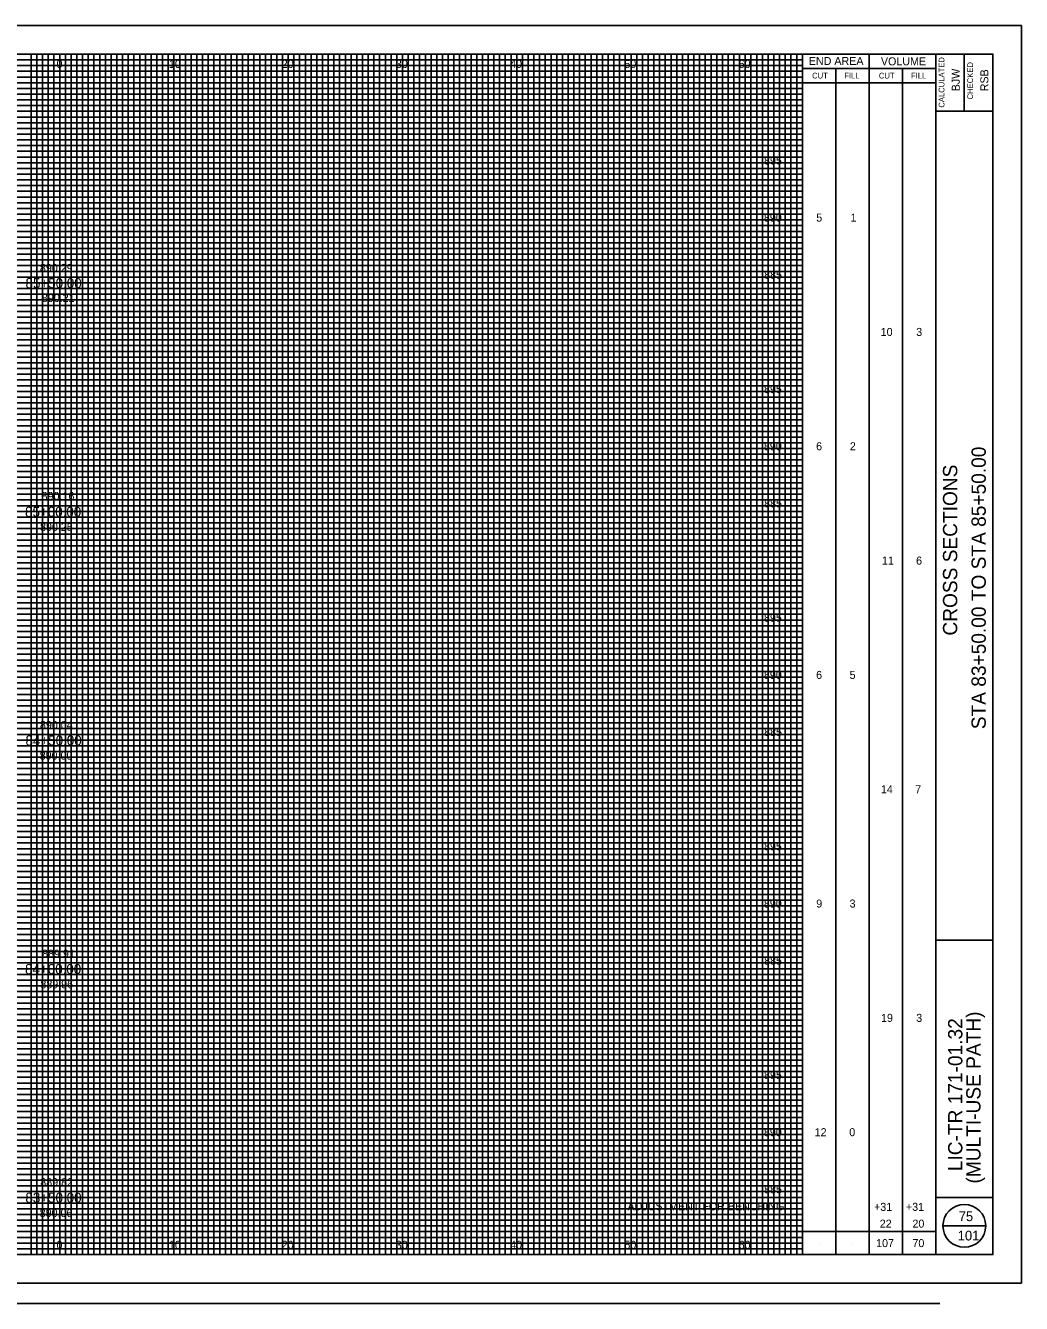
# Model space of a CAD drawing. Extents: x -10 to 160, y -2 to 3672.
# Drawn here: x 72.8 to 160, y 685.7 to 797.5 of the extents above; entities that cross this region are included whole.
import ezdxf

# ---------------------------------------------------------------- set-up
doc = ezdxf.new("R2010")
doc.units = 0
for name, color, linetype in [('SH_Border', 7, 'Continuous'), ('SH_Cut_Line', 7, 'Continuous'), ('SH_Data', 7, 'Continuous'), ('SH_Major_Grid_Line', 7, 'Continuous'), ('SH_Minor_Grid_Line', 7, 'Continuous'), ('SH_Text', 7, 'Continuous'), ('TX_P_10', 7, 'Continuous'), ('TX_X_10', 7, 'Continuous')]:
    doc.layers.add(name, color=color, linetype=linetype)

msp = doc.modelspace()

# ---------------------------------------------------------------- linework, layer by layer
at = {"layer": 'SH_Border'}
for p, q in [((152.5, 690), (152.5, 795)), ((155, 795), (155, 790)), ((152.5, 790), (157.5, 790)), ((152.5, 717.5), (157.5, 717.5)), ((152.5, 695), (157.5, 695))]:
    msp.add_line(p, q, dxfattribs=at)
msp.add_lwpolyline([(0, 795), (157.5, 795), (157.5, 690), (0, 690)], close=True, dxfattribs=at)
at = {"layer": 'SH_Cut_Line'}
msp.add_lwpolyline([(-10, 687.5), (160, 687.5), (160, 797.5), (-10, 797.5)], close=True, dxfattribs=at)
at = {"layer": 'SH_Data'}
for p, q in [((140.83, 690), (140.83, 795)), ((146.67, 690), (146.67, 795)), ((140.83, 793.75), (152.5, 793.75)), ((143.75, 690), (143.75, 793.75)), ((149.58, 690), (149.58, 793.75)), ((140.83, 792.5), (152.5, 792.5)), ((140.83, 692), (152.5, 692)), ((153.12, 692.5), (156.88, 692.5)), ((142.29, 691), (142.29, 691)), ((145.21, 691), (145.21, 691)), ((148.12, 691), (148.12, 691)), ((151.04, 691), (151.04, 691))]:
    msp.add_line(p, q, dxfattribs=at)
msp.add_circle((155, 692.5), 1.87, dxfattribs=at)
at = {"layer": 'SH_Major_Grid_Line'}
for p, q in [((75.83, 690), (75.83, 795)), ((80.83, 690), (80.83, 795)), ((85.83, 690), (85.83, 795)), ((90.83, 690), (90.83, 795)), ((95.83, 690), (95.83, 795)), ((100.83, 690), (100.83, 795)), ((105.83, 690), (105.83, 795)), ((110.83, 690), (110.83, 795)), ((115.83, 690), (115.83, 795)), ((120.83, 690), (120.83, 795)), ((125.83, 690), (125.83, 795)), ((130.83, 690), (130.83, 795)), ((135.83, 690), (135.83, 795)), ((5.83, 790), (140.83, 790)), ((5.83, 785), (140.83, 785)), ((5.83, 780), (140.83, 780)), ((5.83, 775), (140.83, 775)), ((5.83, 770), (140.83, 770)), ((5.83, 765), (140.83, 765)), ((5.83, 760), (140.83, 760)), ((5.83, 755), (140.83, 755)), ((5.83, 750), (140.83, 750)), ((5.83, 745), (140.83, 745)), ((5.83, 740), (140.83, 740)), ((5.83, 735), (140.83, 735)), ((5.83, 730), (140.83, 730)), ((5.83, 725), (140.83, 725)), ((5.83, 720), (140.83, 720)), ((5.83, 715), (140.83, 715)), ((5.83, 710), (140.83, 710)), ((5.83, 705), (140.83, 705)), ((5.83, 700), (140.83, 700)), ((5.83, 695), (140.83, 695)), ((17.85, 685.72), (152.85, 685.72))]:
    msp.add_line(p, q, dxfattribs=at)
at = {"layer": 'SH_Minor_Grid_Line'}
for p, q in [((73.33, 690), (73.33, 795)), ((73.83, 690), (73.83, 795)), ((74.33, 690), (74.33, 795)), ((74.83, 690), (74.83, 795)), ((75.33, 690), (75.33, 795)), ((76.33, 690), (76.33, 795)), ((76.83, 690), (76.83, 795)), ((77.33, 690), (77.33, 795)), ((77.83, 690), (77.83, 795)), ((78.33, 690), (78.33, 795)), ((78.83, 690), (78.83, 795)), ((79.33, 690), (79.33, 795)), ((79.83, 690), (79.83, 795)), ((80.33, 690), (80.33, 795)), ((81.33, 690), (81.33, 795)), ((81.83, 690), (81.83, 795)), ((82.33, 690), (82.33, 795)), ((82.83, 690), (82.83, 795)), ((83.33, 690), (83.33, 795)), ((83.83, 690), (83.83, 795)), ((84.33, 690), (84.33, 795)), ((84.83, 690), (84.83, 795)), ((85.33, 690), (85.33, 795)), ((86.33, 690), (86.33, 795)), ((86.83, 690), (86.83, 795)), ((87.33, 690), (87.33, 795)), ((87.83, 690), (87.83, 795)), ((88.33, 690), (88.33, 795)), ((88.83, 690), (88.83, 795)), ((89.33, 690), (89.33, 795)), ((89.83, 690), (89.83, 795)), ((90.33, 690), (90.33, 795)), ((91.33, 690), (91.33, 795)), ((91.83, 690), (91.83, 795)), ((92.33, 690), (92.33, 795)), ((92.83, 690), (92.83, 795)), ((93.33, 690), (93.33, 795)), ((93.83, 690), (93.83, 795)), ((94.33, 690), (94.33, 795)), ((94.83, 690), (94.83, 795)), ((95.33, 690), (95.33, 795)), ((96.33, 690), (96.33, 795)), ((96.83, 690), (96.83, 795)), ((97.33, 690), (97.33, 795)), ((97.83, 690), (97.83, 795)), ((98.33, 690), (98.33, 795)), ((98.83, 690), (98.83, 795)), ((99.33, 690), (99.33, 795)), ((99.83, 690), (99.83, 795)), ((100.33, 690), (100.33, 795)), ((101.33, 690), (101.33, 795)), ((101.83, 690), (101.83, 795)), ((102.33, 690), (102.33, 795)), ((102.83, 690), (102.83, 795)), ((103.33, 690), (103.33, 795)), ((103.83, 690), (103.83, 795)), ((104.33, 690), (104.33, 795)), ((104.83, 690), (104.83, 795)), ((105.33, 690), (105.33, 795)), ((106.33, 690), (106.33, 795)), ((106.83, 690), (106.83, 795)), ((107.33, 690), (107.33, 795)), ((107.83, 690), (107.83, 795)), ((108.33, 690), (108.33, 795)), ((108.83, 690), (108.83, 795)), ((109.33, 690), (109.33, 795)), ((109.83, 690), (109.83, 795)), ((110.33, 690), (110.33, 795)), ((111.33, 690), (111.33, 795)), ((111.83, 690), (111.83, 795)), ((112.33, 690), (112.33, 795)), ((112.83, 690), (112.83, 795)), ((113.33, 690), (113.33, 795)), ((113.83, 690), (113.83, 795)), ((114.33, 690), (114.33, 795)), ((114.83, 690), (114.83, 795)), ((115.33, 690), (115.33, 795)), ((116.33, 690), (116.33, 795)), ((116.83, 690), (116.83, 795)), ((117.33, 690), (117.33, 795)), ((117.83, 690), (117.83, 795)), ((118.33, 690), (118.33, 795)), ((118.83, 690), (118.83, 795)), ((119.33, 690), (119.33, 795)), ((119.83, 690), (119.83, 795)), ((120.33, 690), (120.33, 795)), ((121.33, 690), (121.33, 795)), ((121.83, 690), (121.83, 795)), ((122.33, 690), (122.33, 795)), ((122.83, 690), (122.83, 795)), ((123.33, 690), (123.33, 795)), ((123.83, 690), (123.83, 795)), ((124.33, 690), (124.33, 795)), ((124.83, 690), (124.83, 795)), ((125.33, 690), (125.33, 795)), ((126.33, 690), (126.33, 795)), ((126.83, 690), (126.83, 795)), ((127.33, 690), (127.33, 795)), ((127.83, 690), (127.83, 795)), ((128.33, 690), (128.33, 795)), ((128.83, 690), (128.83, 795)), ((129.33, 690), (129.33, 795)), ((129.83, 690), (129.83, 795)), ((130.33, 690), (130.33, 795)), ((131.33, 690), (131.33, 795)), ((131.83, 690), (131.83, 795)), ((132.33, 690), (132.33, 795)), ((132.83, 690), (132.83, 795)), ((133.33, 690), (133.33, 795)), ((133.83, 690), (133.83, 795)), ((134.33, 690), (134.33, 795)), ((134.83, 690), (134.83, 795)), ((135.33, 690), (135.33, 795)), ((136.33, 690), (136.33, 795)), ((136.83, 690), (136.83, 795)), ((137.33, 690), (137.33, 795)), ((137.83, 690), (137.83, 795)), ((138.33, 690), (138.33, 795)), ((138.83, 690), (138.83, 795)), ((139.33, 690), (139.33, 795)), ((139.83, 690), (139.83, 795)), ((140.33, 690), (140.33, 795)), ((5.83, 794.5), (140.83, 794.5)), ((5.83, 794), (140.83, 794)), ((5.83, 793.5), (140.83, 793.5)), ((5.83, 793), (140.83, 793)), ((5.83, 792.5), (140.83, 792.5)), ((5.83, 792), (140.83, 792)), ((5.83, 791.5), (140.83, 791.5)), ((5.83, 791), (140.83, 791)), ((5.83, 790.5), (140.83, 790.5)), ((5.83, 789.5), (140.83, 789.5)), ((5.83, 789), (140.83, 789)), ((5.83, 788.5), (140.83, 788.5)), ((5.83, 788), (140.83, 788)), ((5.83, 787.5), (140.83, 787.5)), ((5.83, 787), (140.83, 787)), ((5.83, 786.5), (140.83, 786.5)), ((5.83, 786), (140.83, 786)), ((5.83, 785.5), (140.83, 785.5)), ((5.83, 784.5), (140.83, 784.5)), ((5.83, 784), (140.83, 784)), ((5.83, 783.5), (140.83, 783.5)), ((5.83, 783), (140.83, 783)), ((5.83, 782.5), (140.83, 782.5)), ((5.83, 782), (140.83, 782)), ((5.83, 781.5), (140.83, 781.5)), ((5.83, 781), (140.83, 781)), ((5.83, 780.5), (140.83, 780.5)), ((5.83, 779.5), (140.83, 779.5)), ((5.83, 779), (140.83, 779)), ((5.83, 778.5), (140.83, 778.5)), ((5.83, 778), (140.83, 778)), ((5.83, 777.5), (140.83, 777.5)), ((5.83, 777), (140.83, 777)), ((5.83, 776.5), (140.83, 776.5)), ((5.83, 776), (140.83, 776)), ((5.83, 775.5), (140.83, 775.5)), ((5.83, 774.5), (140.83, 774.5)), ((5.83, 774), (140.83, 774)), ((5.83, 773.5), (140.83, 773.5)), ((5.83, 773), (140.83, 773)), ((5.83, 772.5), (140.83, 772.5)), ((5.83, 772), (140.83, 772)), ((5.83, 771.5), (140.83, 771.5)), ((5.83, 771), (140.83, 771)), ((5.83, 770.5), (140.83, 770.5)), ((5.83, 769.5), (140.83, 769.5)), ((5.83, 769), (140.83, 769)), ((5.83, 768.5), (140.83, 768.5)), ((5.83, 768), (140.83, 768)), ((5.83, 767.5), (140.83, 767.5)), ((5.83, 767), (140.83, 767)), ((5.83, 766.5), (140.83, 766.5)), ((5.83, 766), (140.83, 766)), ((5.83, 765.5), (140.83, 765.5)), ((5.83, 764.5), (140.83, 764.5)), ((5.83, 764), (140.83, 764)), ((5.83, 763.5), (140.83, 763.5)), ((5.83, 763), (140.83, 763)), ((5.83, 762.5), (140.83, 762.5)), ((5.83, 762), (140.83, 762)), ((5.83, 761.5), (140.83, 761.5)), ((5.83, 761), (140.83, 761)), ((5.83, 760.5), (140.83, 760.5)), ((5.83, 759.5), (140.83, 759.5)), ((5.83, 759), (140.83, 759)), ((5.83, 758.5), (140.83, 758.5)), ((5.83, 758), (140.83, 758)), ((5.83, 757.5), (140.83, 757.5)), ((5.83, 757), (140.83, 757)), ((5.83, 756.5), (140.83, 756.5)), ((5.83, 756), (140.83, 756)), ((5.83, 755.5), (140.83, 755.5)), ((5.83, 754.5), (140.83, 754.5)), ((5.83, 754), (140.83, 754)), ((5.83, 753.5), (140.83, 753.5)), ((5.83, 753), (140.83, 753)), ((5.83, 752.5), (140.83, 752.5)), ((5.83, 752), (140.83, 752)), ((5.83, 751.5), (140.83, 751.5)), ((5.83, 751), (140.83, 751)), ((5.83, 750.5), (140.83, 750.5)), ((5.83, 749.5), (140.83, 749.5)), ((5.83, 749), (140.83, 749)), ((5.83, 748.5), (140.83, 748.5)), ((5.83, 748), (140.83, 748)), ((5.83, 747.5), (140.83, 747.5)), ((5.83, 747), (140.83, 747)), ((5.83, 746.5), (140.83, 746.5)), ((5.83, 746), (140.83, 746)), ((5.83, 745.5), (140.83, 745.5)), ((5.83, 744.5), (140.83, 744.5)), ((5.83, 744), (140.83, 744)), ((5.83, 743.5), (140.83, 743.5)), ((5.83, 743), (140.83, 743)), ((5.83, 742.5), (140.83, 742.5)), ((5.83, 742), (140.83, 742)), ((5.83, 741.5), (140.83, 741.5)), ((5.83, 741), (140.83, 741)), ((5.83, 740.5), (140.83, 740.5)), ((5.83, 739.5), (140.83, 739.5)), ((5.83, 739), (140.83, 739)), ((5.83, 738.5), (140.83, 738.5)), ((5.83, 738), (140.83, 738)), ((5.83, 737.5), (140.83, 737.5)), ((5.83, 737), (140.83, 737)), ((5.83, 736.5), (140.83, 736.5)), ((5.83, 736), (140.83, 736)), ((5.83, 735.5), (140.83, 735.5)), ((5.83, 734.5), (140.83, 734.5)), ((5.83, 734), (140.83, 734)), ((5.83, 733.5), (140.83, 733.5)), ((5.83, 733), (140.83, 733)), ((5.83, 732.5), (140.83, 732.5)), ((5.83, 732), (140.83, 732)), ((5.83, 731.5), (140.83, 731.5)), ((5.83, 731), (140.83, 731)), ((5.83, 730.5), (140.83, 730.5)), ((5.83, 729.5), (140.83, 729.5)), ((5.83, 729), (140.83, 729)), ((5.83, 728.5), (140.83, 728.5)), ((5.83, 728), (140.83, 728)), ((5.83, 727.5), (140.83, 727.5)), ((5.83, 727), (140.83, 727)), ((5.83, 726.5), (140.83, 726.5)), ((5.83, 726), (140.83, 726)), ((5.83, 725.5), (140.83, 725.5)), ((5.83, 724.5), (140.83, 724.5)), ((5.83, 724), (140.83, 724)), ((5.83, 723.5), (140.83, 723.5)), ((5.83, 723), (140.83, 723)), ((5.83, 722.5), (140.83, 722.5)), ((5.83, 722), (140.83, 722)), ((5.83, 721.5), (140.83, 721.5)), ((5.83, 721), (140.83, 721)), ((5.83, 720.5), (140.83, 720.5)), ((5.83, 719.5), (140.83, 719.5)), ((5.83, 719), (140.83, 719)), ((5.83, 718.5), (140.83, 718.5)), ((5.83, 718), (140.83, 718)), ((5.83, 717.5), (140.83, 717.5)), ((5.83, 717), (140.83, 717)), ((5.83, 716.5), (140.83, 716.5)), ((5.83, 716), (140.83, 716)), ((5.83, 715.5), (140.83, 715.5)), ((5.83, 714.5), (140.83, 714.5)), ((5.83, 714), (140.83, 714)), ((5.83, 713.5), (140.83, 713.5)), ((5.83, 713), (140.83, 713)), ((5.83, 712.5), (140.83, 712.5)), ((5.83, 712), (140.83, 712)), ((5.83, 711.5), (140.83, 711.5)), ((5.83, 711), (140.83, 711)), ((5.83, 710.5), (140.83, 710.5)), ((5.83, 709.5), (140.83, 709.5)), ((5.83, 709), (140.83, 709)), ((5.83, 708.5), (140.83, 708.5)), ((5.83, 708), (140.83, 708)), ((5.83, 707.5), (140.83, 707.5)), ((5.83, 707), (140.83, 707)), ((5.83, 706.5), (140.83, 706.5)), ((5.83, 706), (140.83, 706)), ((5.83, 705.5), (140.83, 705.5)), ((5.83, 704.5), (140.83, 704.5)), ((5.83, 704), (140.83, 704)), ((5.83, 703.5), (140.83, 703.5)), ((5.83, 703), (140.83, 703)), ((5.83, 702.5), (140.83, 702.5)), ((5.83, 702), (140.83, 702)), ((5.83, 701.5), (140.83, 701.5)), ((5.83, 701), (140.83, 701)), ((5.83, 700.5), (140.83, 700.5)), ((5.83, 699.5), (140.83, 699.5)), ((5.83, 699), (140.83, 699)), ((5.83, 698.5), (140.83, 698.5)), ((5.83, 698), (140.83, 698)), ((5.83, 697.5), (140.83, 697.5)), ((5.83, 697), (140.83, 697)), ((5.83, 696.5), (140.83, 696.5)), ((5.83, 696), (140.83, 696)), ((5.83, 695.5), (140.83, 695.5)), ((5.83, 694.5), (140.83, 694.5)), ((5.83, 694), (140.83, 694)), ((5.83, 693.5), (140.83, 693.5)), ((5.83, 693), (140.83, 693)), ((5.83, 692.5), (140.83, 692.5)), ((5.83, 692), (140.83, 692)), ((5.83, 691.5), (140.83, 691.5)), ((5.83, 691), (140.83, 691)), ((5.83, 690.5), (140.83, 690.5))]:
    msp.add_line(p, q, dxfattribs=at)

# ---------------------------------------------------------------- texts
at = {"layer": 'SH_Data'}
for s, height, p in [('END AREA', 0.7, (141.39, 794.05)), ('VOLUME', 0.7, (147.7, 794.02)), ('CUT', 0.5, (141.68, 792.87)), ('FILL', 0.5, (144.5, 792.87)), ('CUT', 0.5, (147.52, 792.87)), ('FILL', 0.5, (150.34, 792.87)), ('75', 0.85, (154.51, 692.92)), ('101', 0.85, (154.42, 691.23))]:
    msp.add_text(s, height=height, dxfattribs=at).set_placement(p)
for s, height, p in [('CALCULATED', 0.5, (153.26, 790.32)), ('BJW', 0.7, (154.6, 791.75)), ('CHECKED', 0.5, (155.76, 791.04)), ('RSB', 0.7, (157.1, 791.75)), ('STA 83+50.00 TO STA 85+50.00', 1.25, (156.88, 735.95)), ('CROSS SECTIONS', 1.25, (154.38, 744.14)), ('(MULTI-USE PATH)', 1.25, (156.42, 696.21)), ('LIC-TR 171-01.32', 1.25, (154.83, 697.29))]:
    msp.add_text(s, height=height, rotation=90, dxfattribs=at).set_placement(p)
at = {"layer": 'SH_Text'}
for s, height, p in [('0', 0.7, (75.55, 793.79)), ('10', 0.7, (85.39, 793.79)), ('20', 0.7, (95.26, 793.79)), ('30', 0.7, (105.25, 793.79)), ('40', 0.7, (115.25, 793.79)), ('50', 0.7, (125.25, 793.79)), ('60', 0.7, (135.25, 793.79)), ('895', 0.7, (137.47, 785.35)), ('890', 0.7, (137.46, 780.35)), ('5', 0.7, (142.04, 780.35)), ('1', 0.7, (145.04, 780.35)), ('885', 0.7, (137.48, 775.35)), ('85+50.00', 0.875, (72.84, 774.53)), ('10', 0.7, (147.68, 770.35)), ('3', 0.7, (150.79, 770.35)), ('895', 0.7, (137.47, 765.35)), ('890', 0.7, (137.46, 760.35)), ('6', 0.7, (142.03, 760.35)), ('2', 0.7, (144.98, 760.35)), ('885', 0.7, (137.48, 755.35)), ('85+00.00', 0.875, (72.8, 754.53)), ('11', 0.7, (147.79, 750.35)), ('6', 0.7, (150.78, 750.35)), ('895', 0.7, (137.47, 745.35)), ('890', 0.7, (137.46, 740.35)), ('6', 0.7, (142.03, 740.35)), ('5', 0.7, (144.96, 740.35)), ('885', 0.7, (137.48, 735.35)), ('84+50.00', 0.875, (72.84, 734.53)), ('14', 0.7, (147.7, 730.35)), ('7', 0.7, (150.7, 730.35)), ('895', 0.7, (137.47, 725.35)), ('890', 0.7, (137.46, 720.35)), ('9', 0.7, (142.04, 720.35)), ('3', 0.7, (144.96, 720.35)), ('84+00.00', 0.875, (72.8, 714.53)), ('885', 0.7, (137.48, 715.35)), ('19', 0.7, (147.71, 710.35)), ('3', 0.7, (150.79, 710.35)), ('895', 0.7, (137.47, 705.35)), ('890', 0.7, (137.46, 700.35)), ('12', 0.7, (141.9, 700.35)), ('0', 0.7, (144.93, 700.35)), ('83+50.00', 0.875, (72.83, 694.53)), ('885', 0.7, (137.48, 695.35)), ('ADJUSTMENT FOR BENCHING', 0.7, (125.52, 693.87)), ('+31', 0.7, (147.1, 693.82)), ('+31', 0.7, (149.89, 693.82)), ('22', 0.7, (147.6, 692.35)), ('20', 0.7, (150.46, 692.35)), ('0', 0.7, (75.55, 690.5)), ('10', 0.7, (85.39, 690.5)), ('20', 0.7, (95.26, 690.5)), ('30', 0.7, (105.25, 690.5)), ('40', 0.7, (115.25, 690.5)), ('50', 0.7, (125.25, 690.5)), ('60', 0.7, (135.25, 690.5)), ('107', 0.7, (147.28, 690.65)), ('70', 0.7, (150.46, 690.65))]:
    msp.add_text(s, height=height, dxfattribs=at).set_placement(p)
at = {"layer": 'TX_P_10'}
for s, p in [('890.29', (74.1, 775.95)), ('890.16', (74.25, 756)), ('890.04', (74.1, 735.97)), ('889.91', (74.29, 715.97)), ('889.82', (74.13, 695.98))]:
    msp.add_text(s, height=0.7, dxfattribs=at).set_placement(p)
at = {"layer": 'TX_X_10'}
for s, p in [('890.21', (74.27, 773.32)), ('890.25', (74.11, 753.29)), ('890.00', (74.08, 733.29)), ('889.96', (74.14, 713.29)), ('890.06', (74.08, 693.28))]:
    msp.add_text(s, height=0.7, dxfattribs=at).set_placement(p)

doc.saveas('drawing.dxf')
